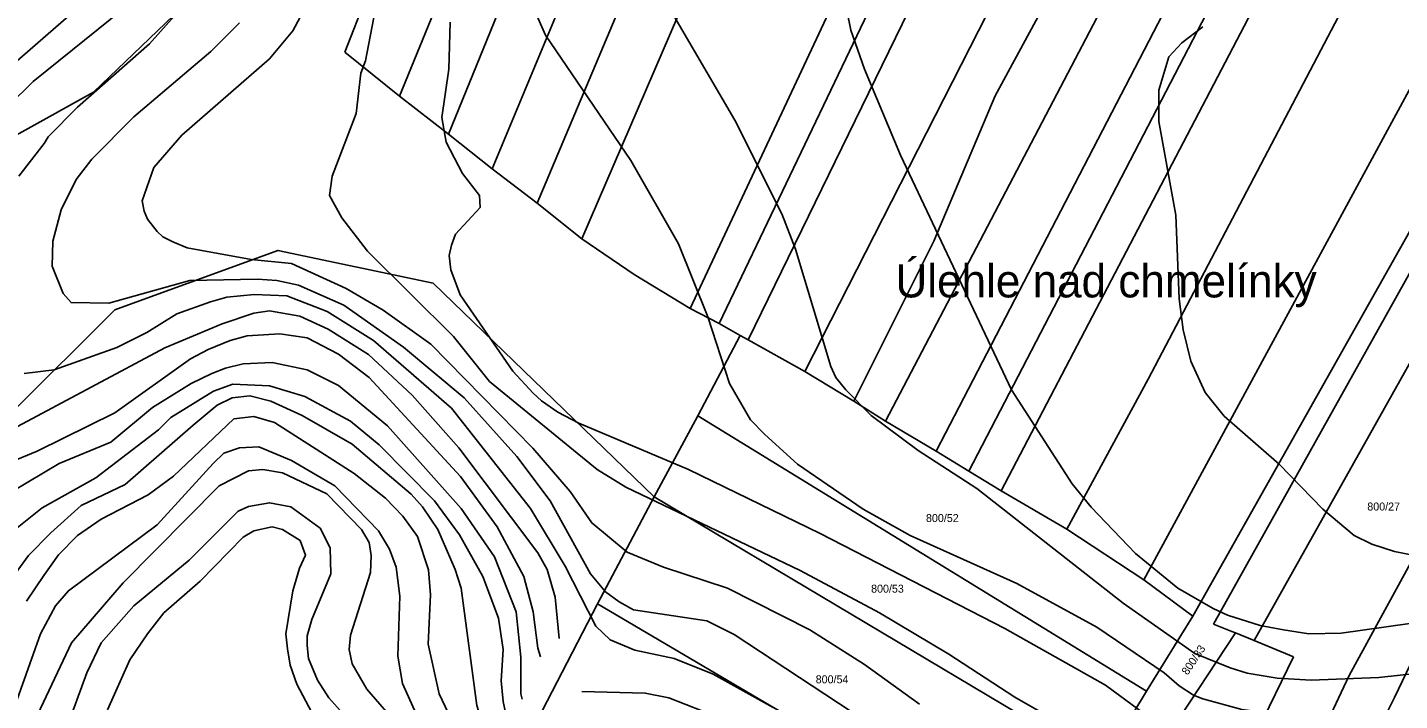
# Model space of a CAD drawing. Extents: x -555860 to -552701, y -1187050 to -1182291.
# Drawn here: x -553802.7 to -553511.2, y -1185998.1 to -1185855 of the extents above; entities that cross this region are included whole.
import ezdxf

# ---------------------------------------------------------------- set-up
doc = ezdxf.new("R2010")
doc.units = 0
for name, color, linetype in [('LEG_2b', 7, 'Continuous'), ('Level 40', 7, 'Continuous'), ('Level 41', 7, 'Continuous'), ('navrh_BV', 7, 'Continuous'), ('Parcelní čísla', 7, 'Continuous'), ('Poz předměty', 7, 'Continuous')]:
    doc.layers.add(name, color=color, linetype=linetype)

msp = doc.modelspace()

# ---------------------------------------------------------------- linework, layer by layer
at = {"layer": 'Level 40'}
for points in [[(-553794.99, -1185788.02), (-553781.4, -1185804.8), (-553777.94, -1185810.06), (-553773.91, -1185820.6), (-553772.53, -1185831.14), (-553773.78, -1185840.29), (-553775.48, -1185843.93), (-553778.07, -1185846.95), (-553782.23, -1185850.97), (-553801.51, -1185866.5), (-553806.78, -1185871.63)], [(-553712.91, -1185853.88), (-553713.18, -1185863.86), (-553714.71, -1185874.12), (-553713.74, -1185879.39), (-553710.27, -1185886.05), (-553706.67, -1185890.76), (-553706.53, -1185893.26), (-553711.8, -1185898.94), (-553712.63, -1185901.3), (-553713.09, -1185903.46), (-553712.77, -1185906.57), (-553710.82, -1185911.84), (-553699.59, -1185928.06), (-553695.3, -1185932.78), (-553693.54, -1185934.4), (-553690.03, -1185936.8), (-553685.59, -1185939.15), (-553662.3, -1185949), (-553634.29, -1185962.59), (-553595.05, -1185982.83), (-553573.69, -1185994.89), (-553558.58, -1186005.99)], [(-553804.83, -1185939.85), (-553773.54, -1185923.09), (-553761.34, -1185918.02), (-553754.62, -1185915.76), (-553751.3, -1185915.23), (-553744.86, -1185916.36), (-553738.85, -1185919.14), (-553730.29, -1185924.53), (-553720.95, -1185933.19), (-553711.1, -1185944.42), (-553694.32, -1185966.75), (-553692.3, -1185970.29), (-553690.58, -1185976.18), (-553689.72, -1185984.95)], [(-553706.05, -1186016.84), (-553707.47, -1186013.14), (-553715.26, -1185996.7), (-553717.62, -1185986.16), (-553717.06, -1185975.62), (-553717.48, -1185970.35), (-553719.84, -1185963.28), (-553723, -1185958.91), (-553726.63, -1185955.1), (-553733.29, -1185949.83), (-553750.2, -1185939.02), (-553754.62, -1185937.7), (-553758.9, -1185938.25), (-553771.7, -1185950.39), (-553777.1, -1185954.41), (-553787.09, -1185959.54), (-553792.08, -1185963), (-553796.1, -1185967.16), (-553799.24, -1185971.53), (-553802.89, -1185977.01)], [(-553613.35, -1186172.24), (-553607.9, -1186156.7), (-553605.25, -1186150.89), (-553602.4, -1186145.89), (-553582.7, -1186118.3), (-553565.79, -1186096.39), (-553557.47, -1186083.5), (-553555.11, -1186078.5), (-553553.17, -1186068.52), (-553554.14, -1186063.53), (-553561.07, -1186056.04), (-553565.51, -1186053.82), (-553593.8, -1186043.84), (-553603.37, -1186039.54), (-553609.6, -1186035.94), (-553620.84, -1186028.17), (-553646.07, -1186007.65), (-553655.64, -1186001.83), (-553666.45, -1185997.53), (-553671.45, -1185996.56), (-553684.92, -1185996.24)]]:
    msp.add_lwpolyline(points, dxfattribs=at)
at = {"layer": 'Level 41'}
for points in [[(-553811.49, -1185764.03), (-553791.5, -1185783.18), (-553787.36, -1185789.13), (-553776.13, -1185803.41), (-553770.29, -1185812.74), (-553763.24, -1185826.7), (-553762.41, -1185830.03), (-553762.54, -1185836.69), (-553764.07, -1185842.79), (-553765.59, -1185845.84), (-553776.82, -1185858.46), (-553792.08, -1185871.91), (-553798.32, -1185878.28), (-553799.15, -1185879.67), (-553804.56, -1185886.6)], [(-553811.49, -1185867.75), (-553791.8, -1185850.69), (-553786.53, -1185844.73), (-553781.82, -1185836.69), (-553780.29, -1185830.59), (-553780.29, -1185826.15), (-553781.68, -1185819.49), (-553784.04, -1185813.11), (-553786.39, -1185808.54), (-553791.8, -1185801.33), (-553794.53, -1185798.34), (-553802.84, -1185792.34)], [(-553699.45, -1185841.12), (-553692.66, -1185856.65), (-553674.5, -1185883.28), (-553664.38, -1185901.02), (-553658.14, -1185916.55), (-553653.56, -1185930.7), (-553649.12, -1185938.46), (-553646.06, -1185941.58), (-553639.14, -1185947.89), (-553625.14, -1185957.46), (-553615.15, -1185963), (-553592.55, -1185973.26), (-553575.49, -1185982.55), (-553561.21, -1185992.26), (-553558.03, -1185995.03), (-553554.97, -1185997.02), (-553553.03, -1185997.8), (-553544.71, -1186000.02), (-553533.07, -1186001.55), (-553523.08, -1186001.83), (-553494.8, -1185999.61)], [(-553494.24, -1185990.87), (-553515.6, -1185993.23), (-553530.02, -1185993.78), (-553537.23, -1185993.37), (-553543.58, -1185992.32), (-553547.21, -1185991.15), (-553554.7, -1185988.1), (-553569.95, -1185977.42), (-553601.01, -1185953.02), (-553613.49, -1185944.98), (-553623.47, -1185937.49), (-553628.88, -1185932.08), (-553630.96, -1185929.45), (-553632.07, -1185927.09), (-553639.56, -1185902.13), (-553642.47, -1185894.65), (-553652.45, -1185874.68), (-553670.06, -1185844.45)], [(-553629.43, -1185847.5), (-553627.77, -1185855.54), (-553624.86, -1185863.86), (-553617.23, -1185882.17), (-553593.66, -1185932.08), (-553580.76, -1185952.05), (-553576.74, -1185957.04), (-553567.32, -1185966.89), (-553558.3, -1185974.23), (-553550.82, -1185978.53), (-553547.79, -1185979.95), (-553540.83, -1185982.14), (-553535.84, -1185983.11), (-553530.46, -1185983.91), (-553523.64, -1185983.8), (-553493.96, -1185979.64)], [(-553613.21, -1185998.91), (-553624.86, -1185990.46), (-553636.51, -1185983.11), (-553653.98, -1185974.23), (-553667.56, -1185969.8), (-553675.33, -1185966.61), (-553682.82, -1185960.37), (-553687.39, -1185953.71), (-553695.32, -1185944.49), (-553717.04, -1185922.36), (-553727.14, -1185915.09), (-553734.99, -1185910.49), (-553746.64, -1185905.22), (-553755.2, -1185904.35), (-553768.78, -1185901.85), (-553771.83, -1185900.61), (-553773.99, -1185899.5), (-553775.16, -1185898.39), (-553777.21, -1185895.79), (-553777.94, -1185894.09), (-553778.35, -1185891.87), (-553775.85, -1185884.8), (-553769.89, -1185877.87), (-553751.31, -1185861.64), (-553746.32, -1185855.68), (-553743.69, -1185850.83)], [(-553728.85, -1185851.38), (-553730.93, -1185862.06), (-553731.9, -1185864.7), (-553732.87, -1185873.29), (-553738, -1185886.6), (-553738.56, -1185890.76), (-553735.92, -1185895.48), (-553730.51, -1185902.55), (-553712.21, -1185920.71), (-553704.58, -1185930.28), (-553681.71, -1185949), (-553675.61, -1185952.74), (-553638.58, -1185970.49), (-553621.67, -1185979.5), (-553606.97, -1185988.24), (-553592.97, -1185997.39), (-553572.72, -1186009.04), (-553564.96, -1186012.5), (-553553.31, -1186015.55), (-553543.6, -1186016.94), (-553524.19, -1186018.47), (-553516.43, -1186019.71), (-553506.72, -1186022.21)], [(-553757.69, -1185854.02), (-553763.79, -1185860.12), (-553780.15, -1185873.98), (-553789.03, -1185883), (-553792.35, -1185887.3), (-553795.54, -1185893.81), (-553797.35, -1185900.47), (-553797.48, -1185905.74), (-553795.13, -1185911.56), (-553793.46, -1185913.5), (-553785.42, -1185913.64), (-553768.23, -1185908.79), (-553753.81, -1185908.51), (-553749.77, -1185908.8), (-553745.14, -1185909.79), (-553735.47, -1185914.07), (-553722.82, -1185923), (-553709.95, -1185933.78), (-553698.76, -1185946.23), (-553691.69, -1185955.66), (-553683.09, -1185971.18), (-553679.92, -1185974.99), (-553676.99, -1185977.15), (-553673.94, -1185978.81), (-553658.41, -1185981.17), (-553652.59, -1185984.08), (-553600.18, -1186018.6)], [(-553553.03, -1185854.85), (-553557.45, -1185858.28), (-553560.24, -1185861.23), (-553562.32, -1185868.3), (-553562.32, -1185874.96), (-553558.72, -1185894.92), (-553558.03, -1185912.67), (-553557.19, -1185919.33), (-553555.53, -1185925.98), (-553552.48, -1185932.64), (-553548.46, -1185937.63), (-553536.81, -1185947.89), (-553527.52, -1185957.46), (-553520.86, -1185963), (-553517.09, -1185964.85), (-553512.27, -1185966.47), (-553498.68, -1185969.1)], [(-553803.45, -1185928.61), (-553797.07, -1185927.78), (-553783.76, -1185923.07), (-553777.38, -1185919.88), (-553771, -1185915.86), (-553763.84, -1185913.36), (-553760.38, -1185912.37), (-553754.53, -1185911.78), (-553747.58, -1185912.07), (-553739.03, -1185915.42), (-553729.18, -1185921.55), (-553712.63, -1185935.97), (-553695.85, -1185957.32), (-553688.5, -1185969.52), (-553681.98, -1185982.28), (-553678.93, -1185985.19), (-553673.67, -1185987.41), (-553665.35, -1185989.21), (-553657.03, -1185992.54), (-553644.27, -1185999.61)], [(-553693.74, -1185988.81), (-553694.32, -1185986.99), (-553695.3, -1185979.23), (-553697.24, -1185971.74), (-553702.92, -1185961.2), (-553710.69, -1185950.52), (-553730.1, -1185929.45), (-553736.61, -1185924.46), (-553743.27, -1185920.99), (-553749.09, -1185920.16), (-553756.03, -1185920.57), (-553759.63, -1185921.53), (-553764.34, -1185923.51), (-553768.05, -1185925.49), (-553784.18, -1185936.94), (-553800.68, -1185945.12), (-553810.52, -1185949.14)], [(-553805.94, -1185953.71), (-553795.96, -1185947.75), (-553785.01, -1185943.18), (-553776.13, -1185935.83), (-553767.95, -1185930.7), (-553763.52, -1185928.61), (-553760.62, -1185927.47), (-553756.86, -1185926.53), (-553750.76, -1185926.26), (-553743.27, -1185927.78), (-553736.61, -1185931.11), (-553726.22, -1185939.71), (-553710.55, -1185957.32), (-553703.48, -1185967.58), (-553698.9, -1185979.23), (-553697.93, -1185988.93), (-553697.93, -1185996.7), (-553697.63, -1185997.81)], [(-553809.69, -1185977.15), (-553802.48, -1185967.3), (-553797.76, -1185962.45), (-553791.32, -1185956.68), (-553781.96, -1185952.19), (-553767.54, -1185939.57), (-553762.41, -1185935.33), (-553759.21, -1185933.73), (-553755.47, -1185933.33), (-553751.04, -1185934.44), (-553744.38, -1185937.49), (-553733.7, -1185943.59), (-553721.22, -1185954.27), (-553718.79, -1185956.93), (-553715.54, -1185961.76), (-553711.86, -1185970.29), (-553710.55, -1185974.24), (-553707.22, -1185999.19), (-553704.18, -1186008.9), (-553703.22, -1186011.09)], [(-553808.85, -1185964.53), (-553799.57, -1185957.18), (-553788.2, -1185950.8), (-553774.88, -1185940.54), (-553772.25, -1185937.91), (-553763.2, -1185932.34), (-553759.11, -1185930.85), (-553751.3, -1185931.22), (-553743.82, -1185933.47), (-553734.12, -1185938.74), (-553728.02, -1185943.73), (-553716.23, -1185955.65), (-553710.96, -1185962.86), (-553705.97, -1185971.74), (-553702.64, -1185980.61), (-553701.67, -1185987.27), (-553702.09, -1185993.92), (-553701.67, -1185998.36), (-553700.4, -1186004.35)], [(-553709.59, -1186024.85), (-553710.27, -1186021.66), (-553712.21, -1186015.83), (-553719.56, -1186002.24), (-553723.03, -1185994.48), (-553724, -1185988.66), (-553723.58, -1185975.9), (-553724.41, -1185969.8), (-553725.8, -1185965.92), (-553728.16, -1185962.03), (-553737.45, -1185952.46), (-553746.6, -1185947.06), (-553753.53, -1185944.15), (-553757.69, -1185944.42), (-553761.02, -1185945.53), (-553763.24, -1185947.75), (-553775.16, -1185960.78), (-553794.02, -1185974.79), (-553796.76, -1185977.97), (-553799.98, -1185983.94), (-553805.25, -1185998.92), (-553808.44, -1186004.6)], [(-553801.7, -1186003.56), (-553793.33, -1185985.88), (-553782.37, -1185973.12), (-553761.99, -1185952.46), (-553755.75, -1185949.28), (-553752.7, -1185949), (-553748.54, -1185949.69), (-553739.09, -1185954.2), (-553731.76, -1185961.76), (-553730.1, -1185964.53), (-553729.68, -1185967.32), (-553729.82, -1185970.91), (-553734.12, -1185984.22), (-553734.4, -1185987.27), (-553733.7, -1185990.32), (-553730.65, -1185995.73), (-553723.72, -1186003.63), (-553719.56, -1186009.73), (-553717.06, -1186015.28), (-553714.01, -1186026.37), (-553712.94, -1186031.2)], [(-553729.54, -1186007.79), (-553738.7, -1185997.53), (-553741.07, -1185993.81), (-553742.99, -1185989.21), (-553743.27, -1185986.44), (-553743.3, -1185984.4), (-553742.3, -1185980.89), (-553738.28, -1185971.18), (-553738.42, -1185965.64), (-553740.5, -1185961.48), (-553746.76, -1185956.93), (-553751.31, -1185956.07), (-553755.75, -1185956.9), (-553757.97, -1185957.87), (-553768.37, -1185968.27), (-553780.15, -1185977.98), (-553787.09, -1185985.88), (-553790.14, -1185992.26), (-553793.27, -1186000.95)], [(-553785.7, -1186000.09), (-553780.98, -1185989.49), (-553777.21, -1185983.91), (-553773.78, -1185979.5), (-553766.01, -1185972.71), (-553756.86, -1185963.42), (-553754.64, -1185962.03), (-553750.76, -1185961.2), (-553748.54, -1185961.76), (-553744.8, -1185964.11), (-553743.68, -1185967.22), (-553744.94, -1185970.01), (-553746.33, -1185974.81), (-553747.85, -1185983.94), (-553747.5, -1185987.12), (-553746.88, -1185990.6), (-553745.49, -1185994.62), (-553739.03, -1186006.84), (-553736.99, -1186013.91)]]:
    msp.add_lwpolyline(points, dxfattribs=at)
at = {"layer": 'navrh_BV'}
for p, q in [((-553735.32, -1185860.26), (-553686.62, -1185736.59)), ((-553723.67, -1185869.57), (-553672.57, -1185744.94)), ((-553713.24, -1185877.69), (-553661.97, -1185751.71)), ((-553703.98, -1185885.06), (-553651.24, -1185758.44)), ((-553694.42, -1185892.33), (-553640.74, -1185764.91)), ((-553684.91, -1185899.93), (-553629.82, -1185771.76)), ((-553661.93, -1185914.73), (-553602.9, -1185788.48)), ((-553596.05, -1185792.97), (-553655.75, -1185917.97)), ((-553649.6, -1185921.39), (-553589.02, -1185797.18)), ((-553575.24, -1185805.65), (-553637.56, -1185928.14)), ((-553597.15, -1185869.55), (-553565.78, -1185811.6)), ((-553556.8, -1185817.16), (-553620.4, -1185938.7)), ((-553609.65, -1185945.12), (-553546.71, -1185823.51)), ((-553539.74, -1185827.85), (-553602.72, -1185949.38)), ((-553595.87, -1185953.5), (-553532.58, -1185832.42)), ((-553564.62, -1185929.77), (-553518.18, -1185841.2)), ((-553565.57, -1185972.44), (-553500.52, -1185852.29)), ((-553723.67, -1185869.57), (-553735.32, -1185860.26)), ((-553487.58, -1185860.21), (-553555.14, -1185980.16)), ((-553550.76, -1185981.91), (-553484.04, -1185862.34)), ((-553476.1, -1185867.4), (-553542.07, -1185985.38)), ((-553713.24, -1185877.69), (-553723.67, -1185869.57)), ((-553610.17, -1185900.44), (-553597.15, -1185869.55)), ((-553703.98, -1185885.06), (-553713.24, -1185877.69)), ((-553512.28, -1185997.48), (-553456.21, -1185879.8)), ((-553694.42, -1185892.33), (-553703.98, -1185885.06)), ((-553684.91, -1185899.93), (-553694.42, -1185892.33)), ((-553673.82, -1185907.56), (-553684.91, -1185899.93)), ((-553627.16, -1185934.46), (-553610.17, -1185900.44)), ((-553661.93, -1185914.73), (-553673.82, -1185907.56)), ((-553655.75, -1185917.97), (-553661.93, -1185914.73)), ((-553651.27, -1185920.48), (-553655.75, -1185917.97)), ((-553651.27, -1185920.48), (-553660.3, -1185937.6)), ((-553649.6, -1185921.39), (-553651.27, -1185920.48)), ((-553637.56, -1185928.14), (-553649.6, -1185921.39)), ((-553627.16, -1185934.46), (-553637.56, -1185928.14)), ((-553581.91, -1185961.7), (-553564.62, -1185929.77)), ((-553620.4, -1185938.7), (-553627.16, -1185934.46)), ((-553660.3, -1185937.6), (-553669.55, -1185954.79)), ((-553564.98, -1185996.15), (-553660.3, -1185937.6)), ((-553609.65, -1185945.12), (-553620.4, -1185938.7)), ((-553602.72, -1185949.38), (-553609.65, -1185945.12)), ((-553595.87, -1185953.5), (-553602.72, -1185949.38)), ((-553581.91, -1185961.7), (-553595.87, -1185953.5)), ((-553669.55, -1185954.79), (-553681.6, -1185977.59)), ((-553574.27, -1186011.58), (-553669.55, -1185954.79)), ((-553565.57, -1185972.44), (-553581.91, -1185961.7)), ((-553521.88, -1185992.82), (-553505.15, -1185962.03)), ((-553555.14, -1185980.16), (-553565.57, -1185972.44)), ((-553681.6, -1185977.59), (-553693.38, -1186000.29)), ((-553589.93, -1186031.52), (-553681.6, -1185977.59)), ((-553564.98, -1185996.15), (-553555.14, -1185980.16)), ((-553546.81, -1185983.47), (-553550.76, -1185981.91)), ((-553566.56, -1186014.89), (-553546.07, -1185983.76)), ((-553546.07, -1185983.76), (-553546.81, -1185983.47)), ((-553542.07, -1185985.38), (-553546.07, -1185983.76)), ((-553542.07, -1185985.38), (-553533.77, -1185988.84)), ((-553549.8, -1186021.77), (-553533.77, -1185988.84)), ((-553538.04, -1186026.86), (-553521.88, -1185992.82)), ((-553574.27, -1186011.58), (-553564.98, -1185996.15)), ((-553528.91, -1186030.63), (-553512.28, -1185997.48))]:
    msp.add_line(p, q, dxfattribs=at)
at = {"layer": 'Poz předměty'}
for points in [[(-553756.31, -1185837.63), (-553788.67, -1185868.78), (-553818.41, -1185885.26), (-553836.14, -1185889.54), (-553848.12, -1185894.51), (-553900.68, -1185960.74)], [(-553868.12, -1185998.62), (-553864.03, -1185991.55), (-553825.07, -1185988.12), (-553813.2, -1185969.07), (-553806.08, -1185936.97), (-553784.19, -1185915.02), (-553749.52, -1185902.39), (-553716.55, -1185909.35), (-553669.55, -1185954.79)]]:
    msp.add_lwpolyline(points, dxfattribs=at)

# ---------------------------------------------------------------- texts
at = {"layer": 'LEG_2b'}
for s, p in [('800/27', (-553518.06, -1185957.72)), ('800/52', (-553611.82, -1185960.17)), ('800/53', (-553623.48, -1185975.19)), ('800/54', (-553635.25, -1185994.47))]:
    msp.add_text(s, height=1.7, dxfattribs=at).set_placement(p)
msp.add_text('800/33', height=1.7, rotation=56, dxfattribs=at).set_placement((-553556.23, -1185992.84))
at = {"layer": 'Parcelní čísla'}
msp.add_text('Úlehle nad chmelínky', height=7, dxfattribs=at).set_placement((-553618.31, -1185912.4))

doc.saveas('drawing.dxf')
